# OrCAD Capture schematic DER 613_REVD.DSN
size Custom; title: USBPD DER613; rev: D
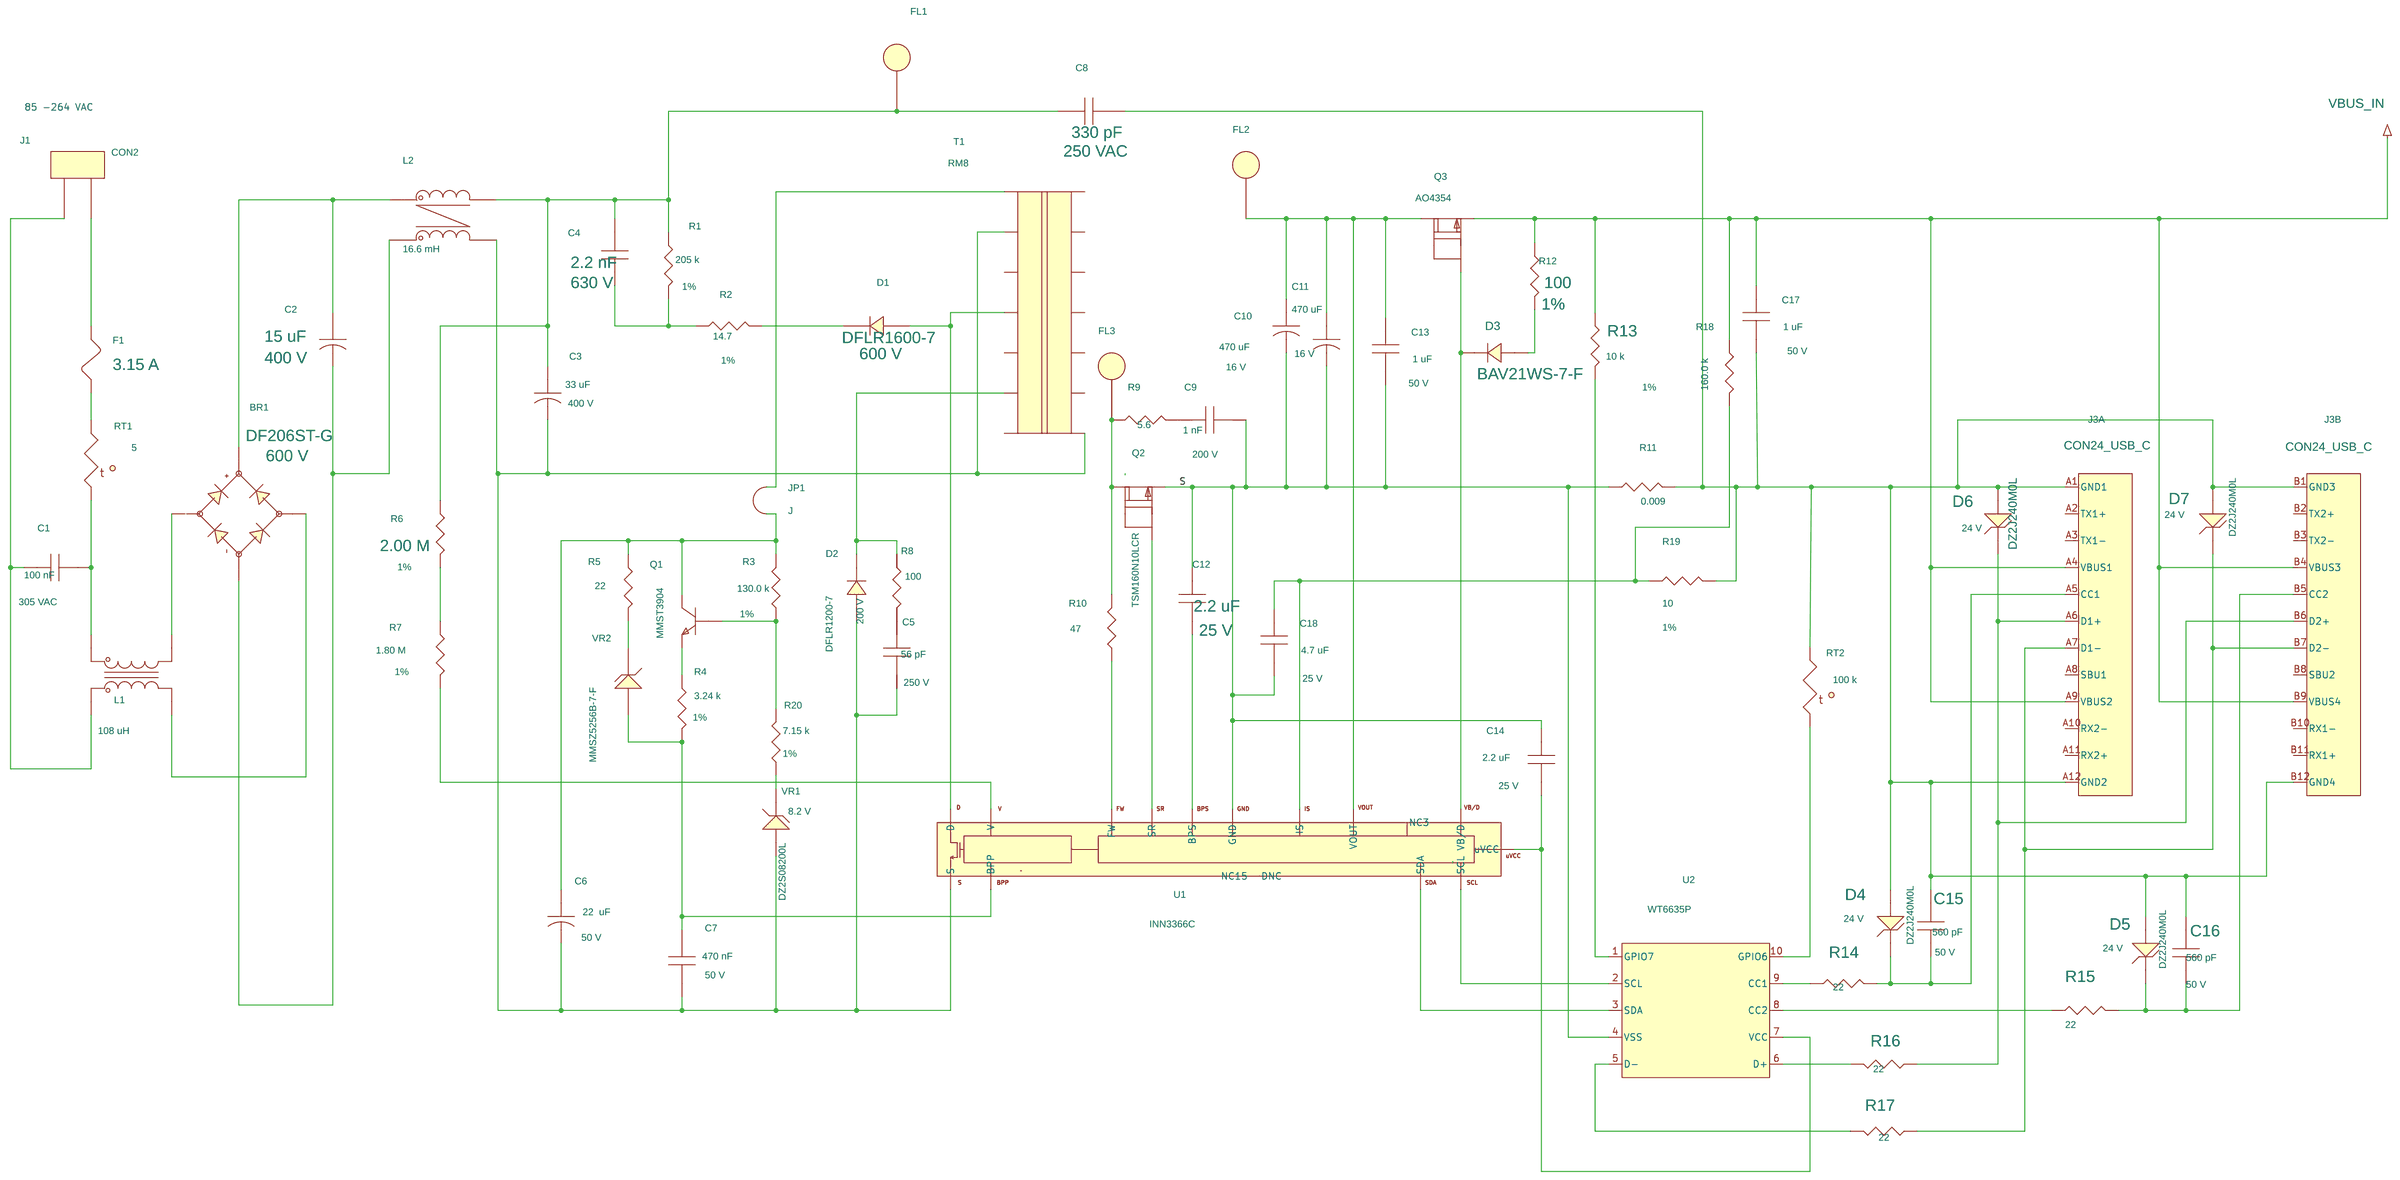
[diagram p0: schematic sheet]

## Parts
BR1  DF206ST-G  [pismddfs]
C1  100 nF  [pi_np_xcap_rad512x197x395d040]
C2  15 uF  [pipolcapcyld400ls200040]
C3  33 uF  [pipolcapclyd500ls200040800lh]
C4  2.2 nF  [pismc1206]
C5  56 pF  [pismc0603]
C6  22  uF  [pipolcapclyd200ls80030]
C7  470 nF  [pismc0805]
C8  330 pF  [pinpcaprad394x275394030]
C9  1 nF  [pismc0805]
C10  470 uF  [pismcpan1VA]
C11  470 uF  [pismcpan1VA]
C12  2.2 uF  [pismc0805]
C13  1 uF  [pismc0805]
C14  2.2 uF  [pismc0805]
C15  560 pF  [pismc0603]
C16  560 pF  [pismc0603]
C17  1 uF  [pismc0805]
C18  4.7 uF  [pismc0805]
D1  DFLR1600-7  [pismddflr120012]
D2  DFLR1200-7  [pismddflr120012]
D3  BAV21WS-7-F  [pismsod323]
D4  DZ2J240M0L  [pi_sm_d_ssmini2p]
D5  DZ2J240M0L  [pi_sm_d_ssmini2p]
D6  DZ2J240M0L  [pi_sm_d_ssmini2p]
D7  DZ2J240M0L  [pi_sm_d_ssmini2p]
F1  3.15 A  [pi_tr5_submin_fuse]
FL1  Hole_50mils  [pi_hole_50mil]
FL2  Hole_70mils  [pi_hole_70mil]
FL3  Hole_70mils  [pi_hole_70mil]
J1  CON2  [pi_pwr_conn_2p_rtang]
J3  CON24_USB_C  [pi_conn_USBC_Wurth]  (sections A,B)
JP1  J  [pi_jumper800]
L1  108 uH  [pi_toroid_cm_choke_4p]
L2  16.6 mH  [pi_toroid_CMC15x7_4p_V]
Q1  MMST3904  [pismsot323132]
Q2  TSM160N10LCR  [pismpqfn5x6b]
Q3  AO4354  [pismso8]
R1  205 k  [pismr1206]
R2  14.7  [pismr1206]
R3  130.0 k  [pismr0402]
R4  3.24 k  [pismr0402]
R5  22  [pismr0402]
R6  2.00 M  [pismr1206]
R7  1.80 M  [pismr1206]
R8  100  [pismr0402]
R9  5.6  [pismr0805]
R10  47  [pismr0402]
R11  0.009  [pismr0805]
R12  100  [pismr0603]
R13  10 k  [pismr0603]
R14  22  [pismr0603]
R15  22  [pismr0603]
R16  22  [pismr0603]
R17  22  [pismr0603]
R18  160.0 k  [pismr0402]
R19  10  [pismr0603]
R20  7.15 k  [pismr0402]
RT1  5  [pi_rad_276DX197T_ls100d025]
RT2  100 k  [pismr0603]
T1  RM8  [pi_bobbin_rm8_12p_clp]
U1  INN3366C  [pi_ic_insop_24d]
U2  WT6635P  [pismsop10]
VR1  DZ2S08200L  [pi_sm_d_ssmini2p]
VR2  MMSZ5256B-7-F  [pi_sm_sod-123_12]

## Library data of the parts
BR1 = DIODE_BRIDGE_+-~~: Disp_Voltage: 600 V; Part Number: 15-00984-00
C1 = CAP_NP: ALT_SYMBOLS: pi_np_xcap_rad512x197x395d040_h; Disp_Voltage: 305 VAC; FPLIST: pi_np_xcap_rad512x197x395d040,pi_np_xcap_rad512x197x395d040_h; Part Number: 20-08957-00; Voltage: 305 VAC
C2 = CAP_POL: ALT_SYMBOLS: pipolcapclyd400x630ls200030h; Disp_Voltage: 400 V; FPLIST: pipolcapcyld400ls200040,pipolcapclyd400x630ls200030h; Part Number: 20-08745-00; Voltage: 400 V
C3 = CAP_POL: Disp_Voltage: 400 V; FPLIST: pipolcapclyd500ls200040,pipolcapclyd500ls200040800lh; Part Number: 20-00888-00; Voltage: 400 V
C4 = CAP_NP: Disp_Voltage: 630 V; Part Number: 20-08609-00; Voltage: 630 V
C5 = CAP_NP: Disp_Voltage: 250 V; Part Number: 20-01325-00; Voltage: 250 V
C6 = CAP_POL: ALT_SYMBOLS: pipolcapclyd200ls80030h; Disp_Voltage: 50 V; FPLIST: pipolcapclyd200ls80030,pipolcapclyd200ls80030h; Part Number: 20-00950-00; Voltage: 50 V
C7 = CAP_NP: Disp_Voltage: 50 V; Part Number: 20-00896-00; Voltage: 50 V
C8 = CAP_NP: Disp_Voltage: 250 VAC; Part Number: 20-00743-00; Voltage: 250 VAC
C9 = CAP_NP: ALT_SYMBOLS: pismc0805_1; Disp_Voltage: 200 V; PCB Editor PCBFP: pismc0603; Part Number: 20-00737-00; Voltage: 200 V
C10 C11 = CAP_POL: Disp_Voltage: 16 V; Part Number: 20-09092-00; Voltage: 16 V
C12 C14 = CAP_NP: Disp_Voltage: 25 V; Part Number: 20-08603-00; Voltage: 25 V
C13 C17 = CAP_NP: Disp_Voltage: 50 V; Part Number: 20-09146-00; Voltage: 50 V
C15 C16 = CAP_NP: Disp_Voltage: 50 V; Part Number: 20-08982-00; Voltage: 50 V
C18 = CAP_NP: Disp_Voltage: 25 V; Part Number: 20-09022-00; Voltage: 25 V
D1 = DIODE: Disp_Voltage: 600 V; Part Number: 15-00826-00
D2 = DIODE: COMPGROUP: 1; Disp_Voltage: 200 V; Part Number: 15-01019-00
D3 = DIODE: COMPGROUP: 1; Part Number: 15-00385-00
D4-D7 = DIODE_ZENER: Disp_Voltage: 24 V; Part Number: 15-01042-00
F1 = FUSE: Part Number: 40-00006-00
FL1 = FlyingLead: Part Number: 35-00283-00
FL2 FL3 = FlyingLead: Part Number: 35-00282-00
J1 = CON2: Part Number: 35-00309-00
J3 = CON24_USB: Part Number: 35-00414-00
JP1 = JUMPER_1: Part Number: 65-00125-00
L1 = INDUCTOR_4P_1-2_4-3: Part Number: 32-00369-00
L2 = TORRID_4P_14_23: Part Number: 32-00368-00
Q1 = NPN_BEC: Part Number: 55-00016-00
Q2 = FET_N_SGD_123_4_5678: Part Number: 50-00280-00
Q3 = FET_N_SGD_123_4_5678: Part Number: 50-00260-00
R1 = R: Disp_Tol: 1%; Part Number: 05-00415-00
R2 = R: Disp_Tol: 1%; Part Number: 05-00017-00
R3 = R: Disp_Tol: 1%; Part Number: 05-06049-00
R4 = R: Disp_Tol: 1%; Part Number: 05-05879-00
R5 = R: Part Number: 05-06177-00
R6 = R: COMPGROUP: 1; Disp_Tol: 1%; Part Number: 05-03156-00
R7 = R: COMPGROUP: 1; Disp_Tol: 1%; Part Number: 05-03155-00
R8 = R: Part Number: 05-06192-00
R9 = R: Part Number: 05-01465-00
R10 = R: Part Number: 05-03426-00
R11 = R: Disp_Tol: 5%; Part Number: 05-06501-00
R12 = R: Disp_Tol: 1%; Part Number: 05-00982-00
R13 = R: Part Number: 05-01712-00
R14-R17 = R: COMPGROUP: 1; Part Number: 05-01648-00
R18 = R: Disp_Tol: 1%; Part Number: 05-06057-00
R19 = R: Disp_Tol: 1%; Part Number: 05-00886-00
R20 = R: Disp_Tol: 1%; Part Number: 05-05920-00
RT1 = THERMISTOR: ALT_SYMBOLS: pi_rad_276DX197Tls100d025H; Part Number: 91-00009-00
RT2 = THERMISTOR: Part Number: 90-00063-00
T1 = BRM8_12P_CLP_0: FPLIST: pi_bobbin_rm8_12p_enertronic,pi_bobbin_rm8_12p_clp; Part Number: 25-01084-00
U1 = DEV_InnoPro: Part Number: 10-01052-00
U2 = WT6635P-10: Part Number: 45-00487-00
VR1 = DIODE_ZENER: Disp_Voltage: 8.2 V; Part Number: 15-01006-00
VR2 = DIODE_ZENER: Part Number: 15-01096-00

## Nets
VBUS_IN: C17.1 J3.A4(VBUS1) J3.A9(VBUS2) J3.B4(VBUS3) J3.B9(VBUS4) Q3.1(S) R12.2 R13.2 R18.1
NC3: U1.3(NC3)
S: C9.2 C10.2 C11.2 C12.1 C13.2 C14.1 C18.2 Q2.1(S) R11.1 U1.2(GND) U2.4(VSS)
N2044610: BR1.1 C2.1 L2.2
N2052921: C10.1 C11.1 C13.1 FL2.1 Q3.5(D) U1.10(VOUT)
N2239928: D1.2 T1.10 U1.24(D)
N2240907: C3.1 C4.2 C8.1 FL1.1 L2.3 R1.2 R6.2
N2243875: C3.2 C5.2 C6.2 C7.2 D2.2 L2.4 T1.2 T1.CLP2 U1.16(S) VR1.2
N2245604: FL3.1 Q2.5(D) R9.2 R10.1
N2254675: C4.1 R1.1 R2.2
N2401179: C8.2 C15.2 C16.2 C17.2 D4.2 D5.2 D6.2 D7.2 J3.A1(GND1) J3.A12(GND2) J3.B1(GND3) J3.B12(GND4) R11.2 R19.2 RT2.1
N2666518: R10.2 U1.11(FW)
N2670154: BR1.2 C2.2 L2.1
N2725054: D2.1 R8.1 T1.12
N2729572: Q2.4(G) U1.9(SR)
N2741729: D1.1 R2.1
N2764626: C1.1 J1.2 L1.1
N2930737: BR1.4 L1.2
N2958561: C7.1 R4.2 U1.14(BPP) VR2.2
N2986761: F1.1 RT1.1
N2989279: BR1.3 L1.3
N2989341: C1.2 L1.4 RT1.2
N2989363: F1.2 J1.1
N2993096: C6.1 JP1.1 Q1.3(COLLECTOR) R3.1 R5.1
N2993205: R5.2 VR2.1
N4181205: R6.1 R7.2
N11157505: C12.2 U1.4(BPS)
N11161568: Q1.1(BASE) R3.2 R20.1
N11380339: R7.1 U1.13(V)
N11380424: JP1.2 T1.1
N11390717: Q1.2(EMITTER) R4.1
N11927756: D3.2 R12.1
N11929917: C14.2 U1.7(uVCC) U2.7(VCC)
N11929995: U1.5(SCL) U2.2(SCL)
N11930002: U1.6(SDA) U2.3(SDA)
N11989159: R13.1 U2.1(GPIO7)
N11989210: RT2.2 U2.10(GPIO6)
N12043478: R16.1 U2.6(D+)
N12043482: R14.2 U2.9(CC1)
N12043490: R15.2 U2.8(CC2)
N12043518: C15.1 D4.1 J3.A5(CC1) R14.1
N12043675: C16.1 D5.1 J3.B5(CC2) R15.1
N12046357: R17.1 U2.5(D-)
N12046915: D7.1 J3.A7(D1-) J3.B7(D2-) R17.2
N12047298: D6.1 J3.A6(D1+) J3.B6(D2+) R16.2
N12057942: C18.1 R18.2 R19.1 U1.1(IS)
N12067975: D3.1 Q3.4(G) U1.8(VB/D)
N12148241: R20.2 VR1.1
N12155048: C9.1 R9.1
N12155049: C5.1 R8.2

Not connected (* = marked no-connect by the designer): J3 A2(TX1+) A3(TX1-) A8(SBU1) A10(RX2-) A11(RX2+) B2(TX2+) B3(TX2-) B8(SBU2) B10(RX1-) B11(RX1+); Q2 2(S2) 3(S3) 6(D6) 7(D7) 8(D8); Q3 2(S2) 3(S3) 6(D6) 7(D7) 8(D8); T1 3 4 5 6 7 8 9 11 CLP1; U1 12(DNC) 15(NC15)

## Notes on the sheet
- 85 -264 VAC
